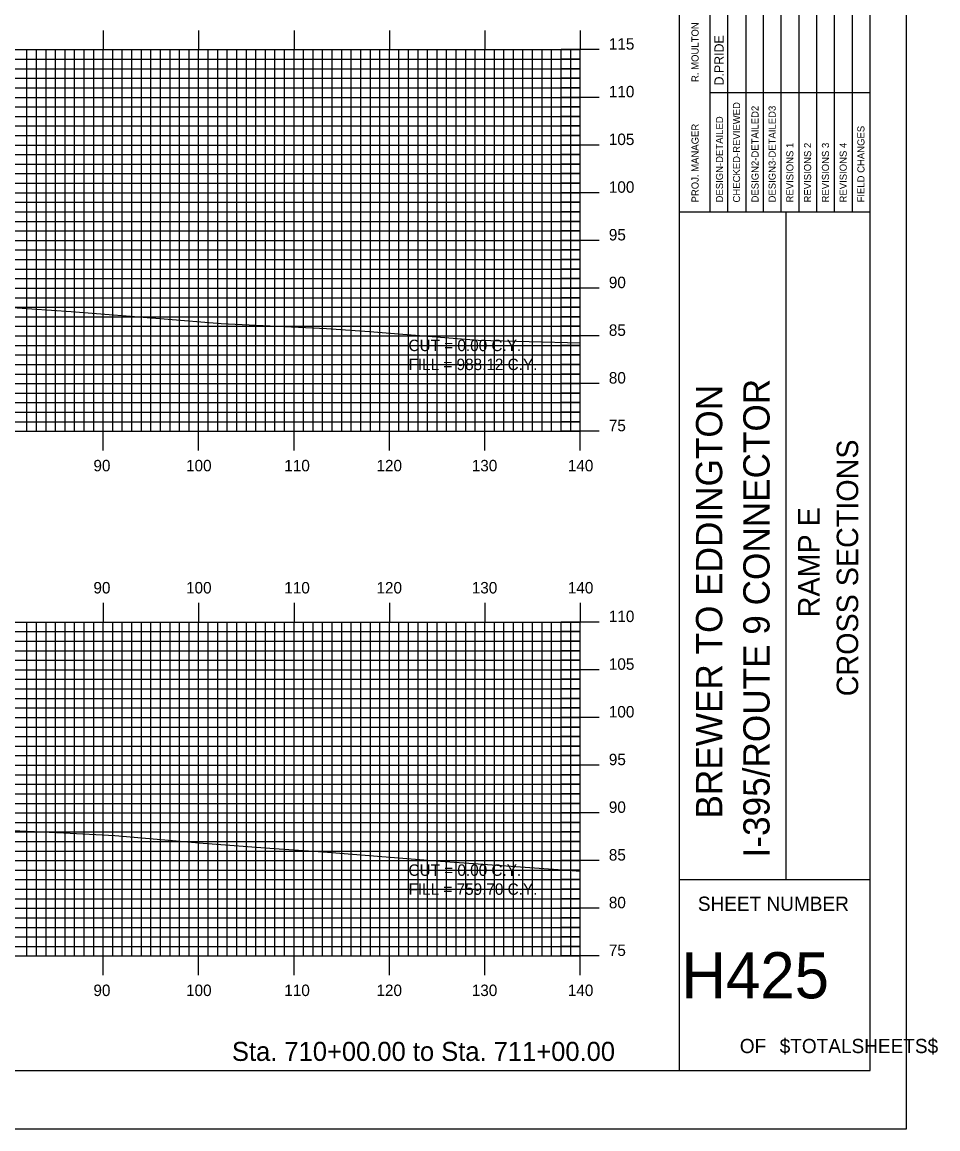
# Model space of a CAD drawing. Extents: x 854903 to 855247, y 364366 to 364586.
# Drawn here: x 855150.8 to 855246.8, y 364365.7 to 364481.7 of the extents above; entities that cross this region are included whole.
import ezdxf

# ---------------------------------------------------------------- set-up
doc = ezdxf.new("R2010")
doc.units = 0
for name, color, linetype in [('BORDER', 7, 'Continuous'), ('D_Text_Standard', 7, 'Continuous'), ('H_V ANNOTATION', 7, 'Continuous'), ('MAJOR', 7, 'Continuous'), ('MINOR', 7, 'Continuous'), ('PLOT BOUNDARY', 7, 'Continuous'), ('S_Roadway_Centerline', 7, 'Continuous')]:
    doc.layers.add(name, color=color, linetype=linetype)

msp = doc.modelspace()

# ---------------------------------------------------------------- linework, layer by layer
at = {"layer": 'BORDER'}
for p, q in [((855219.66, 364371.79), (855219.66, 364581.79)), ((855219.66, 364461.79), (855239.66, 364461.79)), ((855230.84, 364391.79), (855230.84, 364461.79)), ((855219.66, 364391.79), (855239.66, 364391.79))]:
    msp.add_line(p, q, dxfattribs=at)
msp.add_lwpolyline([(854919.66, 364371.79), (855239.66, 364371.79), (855239.66, 364581.79), (854919.66, 364581.79)], close=True, dxfattribs=at)
for points in [[(855224.75, 364461.8), (855224.75, 364496.79)], [(855226.62, 364496.79), (855226.62, 364461.8)], [(855228.48, 364461.8), (855228.48, 364496.79)], [(855230.34, 364461.8), (855230.34, 364496.79)], [(855232.21, 364461.8), (855232.21, 364496.79)], [(855234.07, 364461.8), (855234.07, 364496.79)], [(855235.93, 364461.8), (855235.93, 364496.79)], [(855237.8, 364461.8), (855237.8, 364496.79)], [(855222.89, 364461.8), (855222.89, 364495.38)], [(855222.89, 364474.29), (855239.66, 364474.29)]]:
    msp.add_lwpolyline(points, dxfattribs=at)
at = {"layer": 'MAJOR'}
for p, q in [((855159.26, 364480.79), (855159.26, 364478.79)), ((855169.26, 364480.79), (855169.26, 364478.79)), ((855179.26, 364480.79), (855179.26, 364478.79)), ((855189.26, 364480.79), (855189.26, 364478.79)), ((855199.26, 364480.79), (855199.26, 364478.79)), ((855209.26, 364480.79), (855209.26, 364478.79)), ((854929.26, 364478.79), (855209.26, 364478.79)), ((854929.26, 364478.79), (855209.26, 364478.79)), ((855159.26, 364438.79), (855159.26, 364478.79)), ((855169.26, 364438.79), (855169.26, 364478.79)), ((855179.26, 364438.79), (855179.26, 364478.79)), ((855189.26, 364438.79), (855189.26, 364478.79)), ((855199.26, 364438.79), (855199.26, 364478.79)), ((855211.26, 364478.79), (855207.25, 364478.79)), ((855209.26, 364438.79), (855209.26, 364478.79)), ((855209.26, 364438.79), (855209.26, 364478.79)), ((854929.26, 364473.79), (855209.26, 364473.79)), ((855211.26, 364473.79), (855207.25, 364473.79)), ((854929.26, 364468.79), (855209.26, 364468.79)), ((855211.26, 364468.79), (855207.25, 364468.79)), ((854929.26, 364463.79), (855209.26, 364463.79)), ((855211.26, 364463.79), (855207.25, 364463.79)), ((854929.26, 364458.79), (855209.26, 364458.79)), ((855211.26, 364458.79), (855207.25, 364458.79)), ((854929.26, 364453.79), (855209.26, 364453.79)), ((855211.26, 364453.79), (855207.25, 364453.79)), ((854929.26, 364448.79), (855209.26, 364448.79)), ((855211.26, 364448.79), (855207.25, 364448.79)), ((854929.26, 364443.79), (855209.26, 364443.79)), ((855211.26, 364443.79), (855207.25, 364443.79)), ((854929.26, 364438.79), (855209.26, 364438.79)), ((854929.26, 364438.79), (855209.26, 364438.79)), ((855159.26, 364436.78), (855159.26, 364438.79)), ((855169.26, 364436.78), (855169.26, 364438.79)), ((855179.26, 364436.78), (855179.26, 364438.79)), ((855189.26, 364436.78), (855189.26, 364438.79)), ((855199.26, 364436.78), (855199.26, 364438.79)), ((855211.26, 364438.79), (855207.25, 364438.79)), ((855209.26, 364436.78), (855209.26, 364438.79)), ((855159.26, 364420.79), (855159.26, 364418.79)), ((855169.26, 364420.79), (855169.26, 364418.79)), ((855179.26, 364420.79), (855179.26, 364418.79)), ((855189.26, 364420.79), (855189.26, 364418.79)), ((855199.26, 364420.79), (855199.26, 364418.79)), ((855209.26, 364420.79), (855209.26, 364418.79)), ((854929.26, 364418.79), (855209.26, 364418.79)), ((854929.26, 364418.79), (855209.26, 364418.79)), ((855159.26, 364383.79), (855159.26, 364418.79)), ((855169.26, 364383.79), (855169.26, 364418.79)), ((855179.26, 364383.79), (855179.26, 364418.79)), ((855189.26, 364383.79), (855189.26, 364418.79)), ((855199.26, 364383.79), (855199.26, 364418.79)), ((855211.26, 364418.79), (855207.25, 364418.79)), ((855209.26, 364383.79), (855209.26, 364418.79)), ((855209.26, 364383.79), (855209.26, 364418.79)), ((854929.26, 364413.79), (855209.26, 364413.79)), ((855211.26, 364413.79), (855207.25, 364413.79)), ((854929.26, 364408.79), (855209.26, 364408.79)), ((855211.26, 364408.79), (855207.25, 364408.79)), ((854929.26, 364403.79), (855209.26, 364403.79)), ((855211.26, 364403.79), (855207.25, 364403.79)), ((854929.26, 364398.79), (855209.26, 364398.79)), ((855211.26, 364398.79), (855207.25, 364398.79)), ((854929.26, 364393.79), (855209.26, 364393.79)), ((855211.26, 364393.79), (855207.25, 364393.79)), ((854929.26, 364388.79), (855209.26, 364388.79)), ((855211.26, 364388.79), (855207.25, 364388.79)), ((854929.26, 364383.79), (855209.26, 364383.79)), ((854929.26, 364383.79), (855209.26, 364383.79)), ((855159.26, 364381.78), (855159.26, 364383.79)), ((855169.26, 364381.78), (855169.26, 364383.79)), ((855179.26, 364381.78), (855179.26, 364383.79)), ((855189.26, 364381.78), (855189.26, 364383.79)), ((855199.26, 364381.78), (855199.26, 364383.79)), ((855211.26, 364383.79), (855207.25, 364383.79)), ((855209.26, 364381.78), (855209.26, 364383.79))]:
    msp.add_line(p, q, dxfattribs=at)
at = {"layer": 'MINOR'}
for p, q in [((855151.26, 364438.79), (855151.26, 364478.79)), ((855152.26, 364438.79), (855152.26, 364478.79)), ((855153.26, 364438.79), (855153.26, 364478.79)), ((855154.26, 364438.79), (855154.26, 364478.79)), ((855155.26, 364438.79), (855155.26, 364478.79)), ((855156.26, 364438.79), (855156.26, 364478.79)), ((855157.26, 364438.79), (855157.26, 364478.79)), ((855158.26, 364438.79), (855158.26, 364478.79)), ((855160.26, 364438.79), (855160.26, 364478.79)), ((855161.26, 364438.79), (855161.26, 364478.79)), ((855162.26, 364438.79), (855162.26, 364478.79)), ((855163.26, 364438.79), (855163.26, 364478.79)), ((855164.26, 364438.79), (855164.26, 364478.79)), ((855165.26, 364438.79), (855165.26, 364478.79)), ((855166.26, 364438.79), (855166.26, 364478.79)), ((855167.26, 364438.79), (855167.26, 364478.79)), ((855168.26, 364438.79), (855168.26, 364478.79)), ((855170.26, 364438.79), (855170.26, 364478.79)), ((855171.26, 364438.79), (855171.26, 364478.79)), ((855172.26, 364438.79), (855172.26, 364478.79)), ((855173.26, 364438.79), (855173.26, 364478.79)), ((855174.26, 364438.79), (855174.26, 364478.79)), ((855175.26, 364438.79), (855175.26, 364478.79)), ((855176.26, 364438.79), (855176.26, 364478.79)), ((855177.26, 364438.79), (855177.26, 364478.79)), ((855178.26, 364438.79), (855178.26, 364478.79)), ((855180.26, 364438.79), (855180.26, 364478.79)), ((855181.26, 364438.79), (855181.26, 364478.79)), ((855182.26, 364438.79), (855182.26, 364478.79)), ((855183.26, 364438.79), (855183.26, 364478.79)), ((855184.26, 364438.79), (855184.26, 364478.79)), ((855185.26, 364438.79), (855185.26, 364478.79)), ((855186.26, 364438.79), (855186.26, 364478.79)), ((855187.26, 364438.79), (855187.26, 364478.79)), ((855188.26, 364438.79), (855188.26, 364478.79)), ((855190.26, 364438.79), (855190.26, 364478.79)), ((855191.26, 364438.79), (855191.26, 364478.79)), ((855192.26, 364438.79), (855192.26, 364478.79)), ((855193.26, 364438.79), (855193.26, 364478.79)), ((855194.26, 364438.79), (855194.26, 364478.79)), ((855195.26, 364438.79), (855195.26, 364478.79)), ((855196.26, 364438.79), (855196.26, 364478.79)), ((855197.26, 364438.79), (855197.26, 364478.79)), ((855198.26, 364438.79), (855198.26, 364478.79)), ((855200.26, 364438.79), (855200.26, 364478.79)), ((855201.26, 364438.79), (855201.26, 364478.79)), ((855202.26, 364438.79), (855202.26, 364478.79)), ((855203.26, 364438.79), (855203.26, 364478.79)), ((855204.26, 364438.79), (855204.26, 364478.79)), ((855205.26, 364438.79), (855205.26, 364478.79)), ((855206.26, 364438.79), (855206.26, 364478.79)), ((855207.26, 364438.79), (855207.26, 364478.79)), ((855208.26, 364438.79), (855208.26, 364478.79)), ((854929.26, 364477.79), (855209.26, 364477.79)), ((855209.26, 364477.79), (855207.25, 364477.79)), ((854929.26, 364476.79), (855209.26, 364476.79)), ((854929.26, 364475.79), (855209.26, 364475.79)), ((855209.26, 364476.79), (855207.25, 364476.79)), ((855209.26, 364475.79), (855207.25, 364475.79)), ((854929.26, 364474.79), (855209.26, 364474.79)), ((855209.26, 364474.79), (855207.25, 364474.79)), ((854929.26, 364472.79), (855209.26, 364472.79)), ((855209.26, 364472.79), (855207.25, 364472.79)), ((854929.26, 364471.79), (855209.26, 364471.79)), ((855209.26, 364471.79), (855207.25, 364471.79)), ((854929.26, 364470.79), (855209.26, 364470.79)), ((855209.26, 364470.79), (855207.25, 364470.79)), ((854929.26, 364469.79), (855209.26, 364469.79)), ((855209.26, 364469.79), (855207.25, 364469.79)), ((854929.26, 364467.79), (855209.26, 364467.79)), ((855209.26, 364467.79), (855207.25, 364467.79)), ((854929.26, 364466.79), (855209.26, 364466.79)), ((855209.26, 364466.79), (855207.25, 364466.79)), ((854929.26, 364465.79), (855209.26, 364465.79)), ((855209.26, 364465.79), (855207.25, 364465.79)), ((854929.26, 364464.79), (855209.26, 364464.79)), ((855209.26, 364464.79), (855207.25, 364464.79)), ((854929.26, 364462.79), (855209.26, 364462.79)), ((855209.26, 364462.79), (855207.25, 364462.79)), ((854929.26, 364461.79), (855209.26, 364461.79)), ((854929.26, 364460.79), (855209.26, 364460.79)), ((855209.26, 364461.79), (855207.25, 364461.79)), ((855209.26, 364460.79), (855207.25, 364460.79)), ((854929.26, 364459.79), (855209.26, 364459.79)), ((855209.26, 364459.79), (855207.25, 364459.79)), ((854929.26, 364457.79), (855209.26, 364457.79)), ((855209.26, 364457.79), (855207.25, 364457.79)), ((854929.26, 364456.79), (855209.26, 364456.79)), ((855209.26, 364456.79), (855207.25, 364456.79)), ((854929.26, 364455.79), (855209.26, 364455.79)), ((855209.26, 364455.79), (855207.25, 364455.79)), ((854929.26, 364454.79), (855209.26, 364454.79)), ((855209.26, 364454.79), (855207.25, 364454.79)), ((854929.26, 364452.79), (855209.26, 364452.79)), ((855209.26, 364452.79), (855207.25, 364452.79)), ((854929.26, 364451.79), (855209.26, 364451.79)), ((855209.26, 364451.79), (855207.25, 364451.79)), ((854929.26, 364450.79), (855209.26, 364450.79)), ((855209.26, 364450.79), (855207.25, 364450.79)), ((854929.26, 364449.79), (855209.26, 364449.79)), ((855209.26, 364449.79), (855207.25, 364449.79)), ((854929.26, 364447.79), (855209.26, 364447.79)), ((854929.26, 364446.79), (855209.26, 364446.79)), ((855209.26, 364447.79), (855207.25, 364447.79)), ((855209.26, 364446.79), (855207.25, 364446.79)), ((854929.26, 364445.79), (855209.26, 364445.79)), ((855209.26, 364445.79), (855207.25, 364445.79)), ((854929.26, 364444.79), (855209.26, 364444.79)), ((855209.26, 364444.79), (855207.25, 364444.79)), ((854929.26, 364442.79), (855209.26, 364442.79)), ((855209.26, 364442.79), (855207.25, 364442.79)), ((854929.26, 364441.79), (855209.26, 364441.79)), ((855209.26, 364441.79), (855207.25, 364441.79)), ((854929.26, 364440.79), (855209.26, 364440.79)), ((855209.26, 364440.79), (855207.25, 364440.79)), ((854929.26, 364439.79), (855209.26, 364439.79)), ((855209.26, 364439.79), (855207.25, 364439.79)), ((854929.26, 364417.79), (855209.26, 364417.79)), ((855151.26, 364383.79), (855151.26, 364418.79)), ((855152.26, 364383.79), (855152.26, 364418.79)), ((855153.26, 364383.79), (855153.26, 364418.79)), ((855154.26, 364383.79), (855154.26, 364418.79)), ((855155.26, 364383.79), (855155.26, 364418.79)), ((855156.26, 364383.79), (855156.26, 364418.79)), ((855157.26, 364383.79), (855157.26, 364418.79)), ((855158.26, 364383.79), (855158.26, 364418.79)), ((855160.26, 364383.79), (855160.26, 364418.79)), ((855161.26, 364383.79), (855161.26, 364418.79)), ((855162.26, 364383.79), (855162.26, 364418.79)), ((855163.26, 364383.79), (855163.26, 364418.79)), ((855164.26, 364383.79), (855164.26, 364418.79)), ((855165.26, 364383.79), (855165.26, 364418.79)), ((855166.26, 364383.79), (855166.26, 364418.79)), ((855167.26, 364383.79), (855167.26, 364418.79)), ((855168.26, 364383.79), (855168.26, 364418.79)), ((855170.26, 364383.79), (855170.26, 364418.79)), ((855171.26, 364383.79), (855171.26, 364418.79)), ((855172.26, 364383.79), (855172.26, 364418.79)), ((855173.26, 364383.79), (855173.26, 364418.79)), ((855174.26, 364383.79), (855174.26, 364418.79)), ((855175.26, 364383.79), (855175.26, 364418.79)), ((855176.26, 364383.79), (855176.26, 364418.79)), ((855177.26, 364383.79), (855177.26, 364418.79)), ((855178.26, 364383.79), (855178.26, 364418.79)), ((855180.26, 364383.79), (855180.26, 364418.79)), ((855181.26, 364383.79), (855181.26, 364418.79)), ((855182.26, 364383.79), (855182.26, 364418.79)), ((855183.26, 364383.79), (855183.26, 364418.79)), ((855184.26, 364383.79), (855184.26, 364418.79)), ((855185.26, 364383.79), (855185.26, 364418.79)), ((855186.26, 364383.79), (855186.26, 364418.79)), ((855187.26, 364383.79), (855187.26, 364418.79)), ((855188.26, 364383.79), (855188.26, 364418.79)), ((855190.26, 364383.79), (855190.26, 364418.79)), ((855191.26, 364383.79), (855191.26, 364418.79)), ((855192.26, 364383.79), (855192.26, 364418.79)), ((855193.26, 364383.79), (855193.26, 364418.79)), ((855194.26, 364383.79), (855194.26, 364418.79)), ((855195.26, 364383.79), (855195.26, 364418.79)), ((855196.26, 364383.79), (855196.26, 364418.79)), ((855197.26, 364383.79), (855197.26, 364418.79)), ((855198.26, 364383.79), (855198.26, 364418.79)), ((855200.26, 364383.79), (855200.26, 364418.79)), ((855201.26, 364383.79), (855201.26, 364418.79)), ((855202.26, 364383.79), (855202.26, 364418.79)), ((855203.26, 364383.79), (855203.26, 364418.79)), ((855204.26, 364383.79), (855204.26, 364418.79)), ((855205.26, 364383.79), (855205.26, 364418.79)), ((855206.26, 364383.79), (855206.26, 364418.79)), ((855209.26, 364417.79), (855207.25, 364417.79)), ((855207.26, 364383.79), (855207.26, 364418.79)), ((855208.26, 364383.79), (855208.26, 364418.79)), ((854929.26, 364416.79), (855209.26, 364416.79)), ((855209.26, 364416.79), (855207.25, 364416.79)), ((854929.26, 364415.79), (855209.26, 364415.79)), ((855209.26, 364415.79), (855207.25, 364415.79)), ((854929.26, 364414.79), (855209.26, 364414.79)), ((855209.26, 364414.79), (855207.25, 364414.79)), ((854929.26, 364412.79), (855209.26, 364412.79)), ((855209.26, 364412.79), (855207.25, 364412.79)), ((854929.26, 364411.79), (855209.26, 364411.79)), ((855209.26, 364411.79), (855207.25, 364411.79)), ((854929.26, 364410.79), (855209.26, 364410.79)), ((854929.26, 364409.79), (855209.26, 364409.79)), ((855209.26, 364410.79), (855207.25, 364410.79)), ((855209.26, 364409.79), (855207.25, 364409.79)), ((854929.26, 364407.79), (855209.26, 364407.79)), ((855209.26, 364407.79), (855207.25, 364407.79)), ((854929.26, 364406.79), (855209.26, 364406.79)), ((855209.26, 364406.79), (855207.25, 364406.79)), ((854929.26, 364405.79), (855209.26, 364405.79)), ((855209.26, 364405.79), (855207.25, 364405.79)), ((854929.26, 364404.79), (855209.26, 364404.79)), ((855209.26, 364404.79), (855207.25, 364404.79)), ((854929.26, 364402.79), (855209.26, 364402.79)), ((855209.26, 364402.79), (855207.25, 364402.79)), ((854929.26, 364401.79), (855209.26, 364401.79)), ((855209.26, 364401.79), (855207.25, 364401.79)), ((854929.26, 364400.79), (855209.26, 364400.79)), ((855209.26, 364400.79), (855207.25, 364400.79)), ((854929.26, 364399.79), (855209.26, 364399.79)), ((855209.26, 364399.79), (855207.25, 364399.79)), ((854929.26, 364397.79), (855209.26, 364397.79)), ((855209.26, 364397.79), (855207.25, 364397.79)), ((854929.26, 364396.79), (855209.26, 364396.79)), ((854929.26, 364395.79), (855209.26, 364395.79)), ((855209.26, 364396.79), (855207.25, 364396.79)), ((855209.26, 364395.79), (855207.25, 364395.79)), ((854929.26, 364394.79), (855209.26, 364394.79)), ((855209.26, 364394.79), (855207.25, 364394.79)), ((854929.26, 364392.79), (855209.26, 364392.79)), ((855209.26, 364392.79), (855207.25, 364392.79)), ((854929.26, 364391.79), (855209.26, 364391.79)), ((855209.26, 364391.79), (855207.25, 364391.79)), ((854929.26, 364390.79), (855209.26, 364390.79)), ((855209.26, 364390.79), (855207.25, 364390.79)), ((854929.26, 364389.79), (855209.26, 364389.79)), ((855209.26, 364389.79), (855207.25, 364389.79)), ((854929.26, 364387.79), (855209.26, 364387.79)), ((855209.26, 364387.79), (855207.25, 364387.79)), ((854929.26, 364386.79), (855209.26, 364386.79)), ((855209.26, 364386.79), (855207.25, 364386.79)), ((854929.26, 364385.79), (855209.26, 364385.79)), ((855209.26, 364385.79), (855207.25, 364385.79)), ((854929.26, 364384.79), (855209.26, 364384.79)), ((855209.26, 364384.79), (855207.25, 364384.79))]:
    msp.add_line(p, q, dxfattribs=at)
at = {"layer": 'PLOT BOUNDARY'}
msp.add_lwpolyline([(854903.47, 364365.67), (855243.47, 364365.67), (855243.47, 364585.67), (854903.47, 364585.67)], close=True, dxfattribs=at)
at = {"layer": 'S_Roadway_Centerline'}
for points in [[(855049.55, 364454.18), (855062.67, 364454.82), (855066.55, 364454.86), (855070.93, 364454.85), (855083.24, 364454.52), (855093.81, 364454.09), (855099.2, 364453.86), (855105.68, 364453.68), (855116.43, 364453.65), (855124.27, 364453.53), (855132.86, 364453.16), (855140.6, 364452.69), (855149.71, 364451.76), (855155.88, 364451.34), (855165.66, 364450.59), (855171.63, 364450.07), (855182.67, 364449.57), (855187.18, 364449.24), (855198.56, 364448.34), (855209.26, 364448.06)], [(855048.97, 364399.15), (855058.3, 364398.86), (855066.68, 364398.7), (855075.83, 364398.57), (855085.24, 364398.44), (855092.79, 364398.61), (855098.85, 364398.55), (855110.33, 364398.24), (855113.52, 364398.19), (855126.41, 364397.76), (855130.99, 364397.62), (855141.61, 364397.34), (855144.31, 364397.2), (855155.12, 364396.69), (855160.47, 364396.42), (855169.72, 364395.61), (855177.17, 364395.06), (855182.3, 364394.69), (855194.62, 364393.74), (855208.41, 364392.74), (855209.26, 364392.68)]]:
    msp.add_lwpolyline(points, dxfattribs=at)

# ---------------------------------------------------------------- texts
at = {"layer": 'BORDER'}
for s, height, p in [('R. MOULTON', 0.745, (855221.67, 364475.4)), ('D.PRIDE', 0.969, (855224.3, 364475.04)), ('CHECKED-REVIEWED', 0.7455, (855226.02, 364462.77)), ('DESIGN2-DETAILED2', 0.7455, (855227.96, 364462.77)), ('DESIGN3-DETAILED3', 0.7455, (855229.75, 364462.77)), ('DESIGN-DETAILED', 0.7455, (855224.23, 364462.77)), ('PROJ. MANAGER', 0.7455, (855221.67, 364462.77)), ('FIELD CHANGES', 0.7455, (855239.06, 364462.77)), ('REVISIONS 1', 0.7455, (855231.61, 364462.77)), ('REVISIONS 2', 0.7455, (855233.47, 364462.77)), ('REVISIONS 3', 0.7455, (855235.34, 364462.77)), ('REVISIONS 4', 0.7455, (855237.2, 364462.77)), ('BREWER TO EDDINGTON', 2.7557, (855224.15, 364398.2)), ('I-395/ROUTE 9 CONNECTOR', 2.7557, (855229.11, 364394.12)), ('CROSS SECTIONS', 2.25, (855238.4, 364411.01)), ('RAMP E', 2.25, (855234.35, 364419.29))]:
    msp.add_text(s, height=height, rotation=90, dxfattribs=at).set_placement(p)
for s, height, p in [('SHEET NUMBER', 1.4905, (855221.59, 364388.52)), ('H425', 4.839, (855219.87, 364379.35)), ('OF', 1.491, (855225.99, 364373.61)), ('$TOTALSHEETS$', 1.4905, (855230.17, 364373.61))]:
    msp.add_text(s, height=height, dxfattribs=at).set_placement(p)
at = {"layer": 'D_Text_Standard'}
for s, p in [('CUT = 0.00 C.Y.', (855191.26, 364447.19)), ('FILL = 988.12 C.Y.', (855191.26, 364445.2)), ('CUT = 0.00 C.Y.', (855191.26, 364392.19)), ('FILL = 759.70 C.Y.', (855191.26, 364390.2))]:
    msp.add_text(s, height=1.2, dxfattribs=at).set_placement(p)
at = {"layer": 'H_V ANNOTATION'}
for s, height, p in [('115', 1.2, (855212.26, 364478.79)), ('110', 1.2, (855212.26, 364473.79)), ('105', 1.2, (855212.26, 364468.79)), ('100', 1.2, (855212.26, 364463.79)), ('95', 1.2, (855212.26, 364458.79)), ('90', 1.2, (855212.26, 364453.79)), ('85', 1.2, (855212.26, 364448.79)), ('80', 1.2, (855212.26, 364443.79)), ('75', 1.2, (855212.26, 364438.79)), ('90', 1.2, (855158.23, 364434.59)), ('100', 1.2, (855167.94, 364434.59)), ('110', 1.2, (855178.24, 364434.59)), ('120', 1.2, (855187.9, 364434.59)), ('130', 1.2, (855197.89, 364434.59)), ('140', 1.2, (855207.96, 364434.59)), ('90', 1.2, (855158.23, 364421.79)), ('100', 1.2, (855167.94, 364421.79)), ('110', 1.2, (855178.24, 364421.79)), ('120', 1.2, (855187.9, 364421.79)), ('130', 1.2, (855197.89, 364421.79)), ('140', 1.2, (855207.96, 364421.79)), ('110', 1.2, (855212.26, 364418.79)), ('105', 1.2, (855212.26, 364413.79)), ('100', 1.2, (855212.26, 364408.79)), ('95', 1.2, (855212.26, 364403.79)), ('90', 1.2, (855212.26, 364398.79)), ('85', 1.2, (855212.26, 364393.79)), ('80', 1.2, (855212.26, 364388.79)), ('75', 1.2, (855212.26, 364383.79)), ('90', 1.2, (855158.23, 364379.59)), ('100', 1.2, (855167.94, 364379.59)), ('110', 1.2, (855178.24, 364379.59)), ('120', 1.2, (855187.9, 364379.59)), ('130', 1.2, (855197.89, 364379.59)), ('140', 1.2, (855207.96, 364379.59)), ('Sta. 710+00.00 to Sta. 711+00.00', 2.0004, (855172.75, 364372.79))]:
    msp.add_text(s, height=height, dxfattribs=at).set_placement(p)

doc.saveas('drawing.dxf')
